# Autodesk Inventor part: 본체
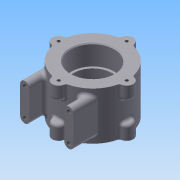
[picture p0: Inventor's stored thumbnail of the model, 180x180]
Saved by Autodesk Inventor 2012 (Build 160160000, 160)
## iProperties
Created: 2015-03
Part Number: 본체
Material: 알루미늄-6061
Document SubType Name: Modeling
Designer: net
Density: 2.71 g/cm^3
Mass: 438.468 g
Surface Area: 321.729 cm^2
Volume: 161.796 cm^3
Author: net
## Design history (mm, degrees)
sketch "스케치1"
  geometry: C1 r 37 at (0, 0); 1 further point
  constraints: 1 centre point, 1 coincident
  dimensions: "d0" = 74 diameter of C1
extrude "돌출1" new body sketch "스케치1" distance "d1" = 52; taper "d2" = 0 deg
node "작업 평면1"
sketch "스케치2"
  geometry: L1 (-29, 6)-(-19, 6); L2 (-19, 6)-(-19, 46); L3 (-19, 46)-(-29, 46); L4 (-29, 46)-(-29, 6); L5 (-37, 0)-(-37, 52) reference; L6 (29, 6)-(19, 6); L7 (19, 6)-(19, 46); L8 (19, 46)-(29, 46); L9 (29, 46)-(29, 6); 1 further point
  constraints: 16 end point, 2 parallel, 1 horizontal, 1 perpendicular
  dimensions: "d4" = 40 distance of L3.end L1.start; "d6" = 10 distance of L1.start L1.end
extrude "돌출2" join sketch "스케치2" stored distance "d8" = 52; taper "d9" = 0 deg
fillet "모깎기1" dims "d10" = 5
fillet "모깎기2" dims "d11" = 3
sketch "스케치4"
  geometry: L1 (-7, 37)-(-7, 36.332); L2 (7, 37)-(7, 36.332); A1 r 37 centre (0, 0) between (0, 37) and (-7, 36.332) reference; A2 r 7 centre (0, 37) between (7, 37) and (-7, 37)
  constraints: 5 point on circle, 4 end point, 1 centre point, 1 tangent, 1 vertical
extrude "돌출4" join sketch "스케치4" distance "d20" = 15; taper "d21" = 0 deg
fillet "모깎기3" dims "d22" = 3
sketch "스케치5"
  geometry: C1 r 7 at (0, 37); 1 further point
  constraints: 1 centre point, 1 vertical alignment, 1 other
  dimensions: "d26" = 14 diameter of C1
extrude "돌출5" join sketch "스케치5" distance "d27" = 15; taper "d28" = 0 deg
fillet "모깎기4" dims "d29" = 3
hole "구멍1" diameter "d32" = 4.134; stored, may be unused: countersink angle "d36" = 90 deg, drill point angle "d38" = 118 deg; dims "d30" = 10, "d31" = 10, "d33" = 6, "d34" = 4, "d35" = 2, "d37" = 8
hole "구멍2" diameter "d41" = 4.134; stored, may be unused: countersink angle "d45" = 90 deg, drill point angle "d47" = 118 deg; dims "d39" = 10, "d40" = 10, "d42" = 6, "d43" = 4, "d44" = 2, "d46" = 8
hole "구멍3" diameter "d50" = 4.134; stored, may be unused: countersink angle "d54" = 90 deg, drill point angle "d56" = 118 deg; dims "d48" = 10, "d49" = 10, "d51" = 6, "d52" = 4, "d53" = 2, "d55" = 8
hole "구멍4" diameter "d59" = 4.134; stored, may be unused: countersink angle "d63" = 90 deg, drill point angle "d65" = 118 deg; dims "d57" = 10, "d58" = 10, "d60" = 6, "d61" = 4, "d62" = 2, "d64" = 8
hole "구멍5" diameter "d71" = 3.242; stored, may be unused: countersink angle "d75" = 90 deg, drill point angle "d77" = 118 deg; dims "d69" = 10, "d70" = 10, "d72" = 8, "d73" = 4, "d74" = 2, "d76" = 11
hole "구멍6" diameter "d83" = 3.242; stored, may be unused: countersink angle "d87" = 90 deg, drill point angle "d89" = 118 deg; dims "d81" = 10, "d82" = 10, "d84" = 8, "d85" = 4, "d86" = 2, "d88" = 11
hole "구멍7" diameter "d95" = 42; stored, may be unused: countersink angle "d99" = 90 deg, drill point angle "d101" = 118 deg; dims "d93" = 10, "d94" = 10, "d96" = 8, "d97" = 47, "d98" = 22, "d100" = 11
hole "구멍8" diameter "d104" = 47; stored, may be unused: countersink angle "d108" = 90 deg, drill point angle "d110" = 0 deg; dims "d105" = 8, "d106" = 47, "d107" = 22, "d109" = 22, "d131" = 10, "d132" = 10
fillet "모깎기5" dims "d111" = 0.3
chamfer "모따기1" distance "d112" = 1; stored, may be unused: second distance "d113" = 2, angle "d114" = 45 deg
chamfer "모따기2" distance "d115" = 1; stored, may be unused: second distance "d116" = 2, angle "d117" = 45 deg
node "작업 평면9"
sketch "스케치12"
  geometry: 2 further points
  constraints: 1 other
  dimensions: "d127" = 0 horizontal distance of point (0, -52) point (0, -26); "d128" = 26 distance of point (0, -26) point (0, -52)
feature "엠보싱2" sketch "스케치12" dims "d1" = 52, "d10" = 5, "d129" = 0.5, "d130" = 0
node "솔리드1"
pattern_circular "원형 패턴1" dims angle "d24" = 360 deg
pattern_circular "원형 패턴2" dims angle "d67" = 360 deg
pattern_circular "원형 패턴3" dims angle "d79" = 360 deg
pattern_circular "원형 패턴4" dims angle "d91" = 360 deg
other parameters: "d12" = 15, "d14" = 7, "d18" = 14, "d19" = 14
